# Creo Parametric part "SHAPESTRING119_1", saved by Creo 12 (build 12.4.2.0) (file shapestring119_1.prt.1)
Units: Custom; MM, KILOGRAM, SECS

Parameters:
  PTC_WM_ITERATION = "0"
  PTC_WM_VERSION = "-.0"
  PTC_WM_LIFECYCLE_STATE = "In Work"
  PTC_WM_LIFECYCLE = "MO_CADDocument"
  PTC_WM_CREATED_BY = "Maximilian Roepper (Z0017RMS: MO)"
  PTC_WM_CREATED_ON = "18-Sep-26 11:36:42 AM"
  PTC_WM_MODIFIED_BY = "Maximilian Roepper (Z0017RMS: MO)"
  PTC_WM_MODIFIED_ON = "18-Sep-26 11:36:46 AM"
  PDMLINKNUMBER = "PDM000071455117"
  PTC_WM_NAME = "shapestring119_1.prt"
  PTC_WM_NUMBER = "PDM000071455117"

Other parameters: WEIGHT, WEIGHT_FACTOR, WEIGHT_ADD, _MASS_TEMP, _DIFF_TEMP, MC_ERRORS, SUPPLIER

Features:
  1. coordinate system
  2. datum plane "PRT_YZ"
  3. datum plane "PRT_XY"
  4. datum plane "PRT_XZ"
  5. coordinate system
  6. datum axis
  7. datum axis
  8. datum axis
  9. coordinate system
  10. imported feature

Other named items: PRT, SIEMENS_MO, DRW_VIEW_ORG, PRT_X, PRT_Y, PRT_Z, CS0, ROUGH_GROB

Layers: 00_STD_CSYS-KSYS, 01_STD_PLANES-EBENEN, 02_STD_AXES-ACHSEN, 03_STD_CSYS-KSYS, 24_IMPORT_FEAT-IMPORT_KE, INTFCLR

Surfaces: 1 plane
